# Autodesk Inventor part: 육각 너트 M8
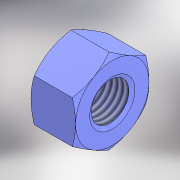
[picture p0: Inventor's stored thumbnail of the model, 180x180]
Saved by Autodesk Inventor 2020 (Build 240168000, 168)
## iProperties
Created: 2024-11
Part Number: 육각 너트 M8
Material: 강철, 연강
Description: 6각 너트 및 6각 가는 너트
Document SubType Name: Modeling
Designer: shin
Density: 7.85 g/cm^3
Appearance: 기본값
Sending System: Autodesk Inventor 2025
Preprocessor: ST-DEVELOPER v20
Author: jhkim
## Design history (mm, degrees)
feature "Solid1"
feature "스레드1" dims "d0" = 7.119, "d1" = 0
node "솔리드1"
feature "A9D066F2-1C7D-4E18-AEED-F7BC21143FA4" dims "d0" = 7.119, "d1" = 0
